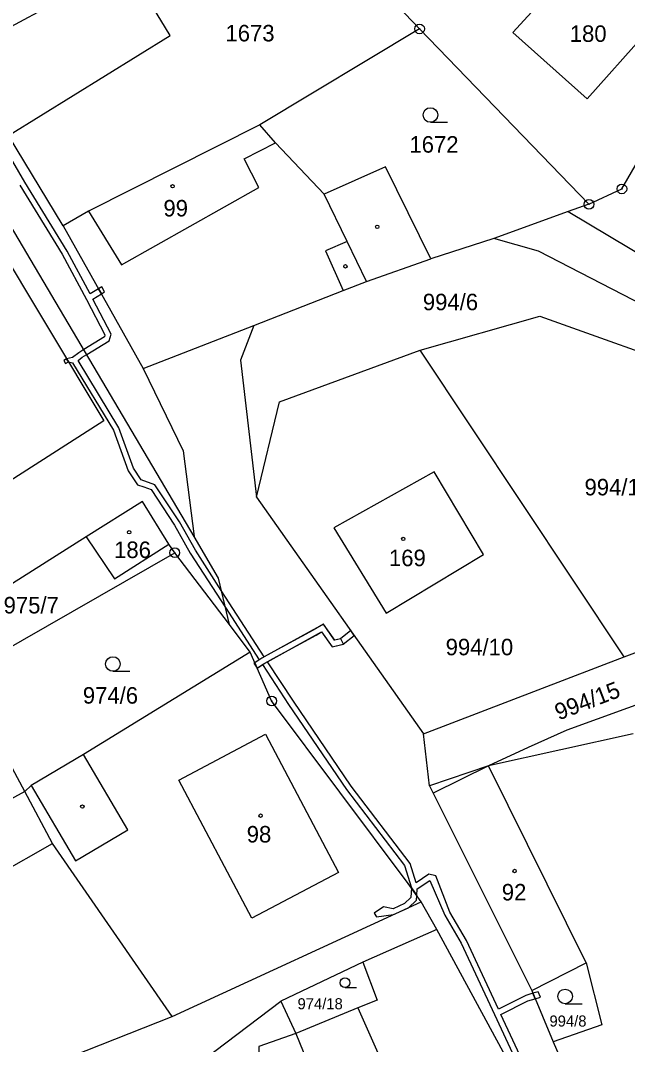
# Model space of a CAD drawing. Extents: x -680203 to -673936, y -1102717 to -1093650.
# Drawn here: x -676663.1 to -676600.6, y -1100837.8 to -1100732.3 of the extents above; entities that cross this region are included whole.
import ezdxf

# ---------------------------------------------------------------- set-up
doc = ezdxf.new("R2010")
doc.units = 0
for name, color, linetype in [('SOxx02xx_Koleje_param další_Popis10', 7, 'Continuous'), ('SOxxxxxx_Koleje_hlavní_body_Popis10', 7, 'Continuous'), ('SOxxxxxx_Koleje_LN_parametry_Popis10', 7, 'Continuous'), ('SOxxxxxx_Koleje_param další_Popis10', 7, 'Continuous'), ('SOxxxxxx_Osa_bod_P', 7, 'Continuous'), ('SOxxxxxx_Staničení_Popis10', 7, 'Continuous'), ('x_prac', 7, 'Continuous')]:
    doc.layers.add(name, color=color, linetype=linetype)

msp = doc.modelspace()

# ---------------------------------------------------------------- linework, layer by layer
at = {"layer": 'SOxx02xx_Koleje_param další_Popis10'}
for centre, radius in [((-676622.04, -1100733.21), 0.5), ((-676622.04, -1100733.21), 0.0303), ((-676601.2, -1100749.69), 0.5), ((-676601.2, -1100749.69), 0.0303), ((-676604.59, -1100751.28), 0.5), ((-676604.59, -1100751.28), 0.0303), ((-676647.25, -1100787.16), 0.5), ((-676647.25, -1100787.16), 0.0303), ((-676637.28, -1100802.43), 0.5), ((-676637.28, -1100802.43), 0.0303)]:
    msp.add_circle(centre, radius, dxfattribs=at)
at = {"layer": 'SOxxxxxx_Koleje_hlavní_body_Popis10'}
for p, q in [((-676620.92, -1100742.83), (-676619.17, -1100742.83)), ((-676653.62, -1100799.38), (-676651.87, -1100799.38)), ((-676629.71, -1100831.95), (-676628.54, -1100831.95)), ((-676607.05, -1100833.62), (-676605.3, -1100833.62))]:
    msp.add_line(p, q, dxfattribs=at)
for centre, radius in [((-676620.92, -1100742.08), 0.75), ((-676653.62, -1100798.63), 0.75), ((-676629.72, -1100831.45), 0.502), ((-676607.05, -1100832.87), 0.75)]:
    msp.add_circle(centre, radius, dxfattribs=at)
at = {"layer": 'SOxxxxxx_Koleje_LN_parametry_Popis10'}
for points in [[(-676610.13, -1100833.1), (-676610.36, -1100832.54), (-676611.11, -1100832.76), (-676613.92, -1100834.19), (-676617.2, -1100827.1), (-676618.93, -1100824.2), (-676620.38, -1100820.46), (-676621.08, -1100820.27), (-676622.4, -1100821.15), (-676623.01, -1100819.19), (-676629.08, -1100811.22), (-676635.03, -1100802.47), (-676637.7, -1100798.39), (-676632.13, -1100795.3), (-676631.04, -1100796.85), (-676629.89, -1100796.57), (-676630.16, -1100796.02), (-676630.78, -1100796.17), (-676631.95, -1100794.52), (-676638.03, -1100797.88), (-676642.46, -1100791.04), (-676645.13, -1100786.9), (-676646.75, -1100783.99), (-676649.29, -1100780.16), (-676650.72, -1100779.67), (-676651.51, -1100778.46), (-676653.01, -1100774.29), (-676657.21, -1100767.37), (-676656.78, -1100767.04), (-676656.32, -1100766.76), (-676654, -1100765.35), (-676653.79, -1100764.65), (-676655.69, -1100761.04), (-676654.81, -1100760.51), (-676655.11, -1100759.99), (-676655.97, -1100760.51), (-676658.34, -1100756.12), (-676662.7, -1100749.01), (-676666.3, -1100742.87)], [(-676663.22, -1100749.32), (-676658.86, -1100756.42), (-676656.35, -1100761.07), (-676654.44, -1100764.71), (-676654.5, -1100764.93), (-676656.63, -1100766.24), (-676657.14, -1100766.56), (-676657.78, -1100767.06), (-676658.39, -1100767.18), (-676658.21, -1100767.49), (-676657.77, -1100767.61), (-676653.55, -1100774.55), (-676652.05, -1100778.72), (-676651.1, -1100780.17), (-676650.44, -1100780.39), (-676649.67, -1100780.66), (-676647.27, -1100784.31), (-676645.65, -1100787.2), (-676642.03, -1100792.8), (-676638.55, -1100798.19), (-676639.01, -1100798.49), (-676638.77, -1100799.04), (-676638.22, -1100798.69), (-676635.53, -1100802.81), (-676629.58, -1100811.56), (-676623.59, -1100819.37), (-676622.88, -1100821.68), (-676622.33, -1100822.46), (-676622.28, -1100821.79), (-676620.98, -1100820.92), (-676619.45, -1100824.5), (-676617.74, -1100827.38), (-676614.33, -1100834.73), (-676610.64, -1100842.63)], [(-676609.97, -1100842.66), (-676613.67, -1100834.74), (-676610.89, -1100833.32), (-676610.13, -1100833.1)]]:
    msp.add_lwpolyline(points, dxfattribs=at)
for points in [[(-676654.77, -1100759.78), (-676655.11, -1100759.99), (-676654.81, -1100760.51), (-676654.48, -1100760.31)], [(-676658.51, -1100767.67), (-676658.21, -1100767.49), (-676658.39, -1100767.18), (-676658.69, -1100767.36)], [(-676638.28, -1100798.02), (-676639.01, -1100798.49), (-676638.77, -1100799.04), (-676637.98, -1100798.54), (-676637.13, -1100798.07), (-676632.7, -1100795.65), (-676632.13, -1100795.31), (-676631.04, -1100796.85), (-676629.92, -1100796.58), (-676628.77, -1100795.68), (-676629.12, -1100795.19), (-676630.18, -1100796.02), (-676630.8, -1100796.17), (-676631.95, -1100794.51), (-676633, -1100795.13), (-676637.41, -1100797.55)], [(-676630.8, -1100796.17), (-676631.95, -1100794.51), (-676633, -1100795.13), (-676637.41, -1100797.55), (-676638.28, -1100798.02), (-676639.01, -1100798.49), (-676638.77, -1100799.04), (-676637.98, -1100798.54), (-676637.13, -1100798.07), (-676632.7, -1100795.65), (-676632.13, -1100795.31), (-676631.04, -1100796.85), (-676629.92, -1100796.58), (-676628.77, -1100795.68), (-676629.12, -1100795.19), (-676630.18, -1100796.02)], [(-676638.77, -1100799.04), (-676639.01, -1100798.49), (-676639.11, -1100798.55)], [(-676622.33, -1100822.46), (-676622.88, -1100821.68), (-676622.94, -1100822.68), (-676623.6, -1100823.3), (-676624.76, -1100823.84), (-676625.74, -1100823.64), (-676626.71, -1100824.28), (-676626.46, -1100824.66), (-676624.72, -1100824.44), (-676623.19, -1100823.74), (-676622.36, -1100822.95)], [(-676609.84, -1100832.38), (-676610.36, -1100832.54), (-676610.13, -1100833.1), (-676609.58, -1100832.93)]]:
    msp.add_lwpolyline(points, close=True, dxfattribs=at)
at = {"layer": 'SOxxxxxx_Koleje_param další_Popis10'}
for centre in [(-676647.48, -1100749.42), (-676626.4, -1100753.6), (-676629.68, -1100757.67), (-676651.95, -1100785.06), (-676623.72, -1100785.74), (-676656.77, -1100813.31), (-676638.41, -1100814.25), (-676612.25, -1100819.95)]:
    msp.add_circle(centre, 0.175, dxfattribs=at)
at = {"layer": 'SOxxxxxx_Staničení_Popis10'}
for p, q in [((-676666.5, -1100734.25), (-676652.22, -1100726.48)), ((-676640.09, -1100746.61), (-676636.87, -1100744.96)), ((-676638.58, -1100749.56), (-676640.09, -1100746.61)), ((-676652.75, -1100757.53), (-676638.58, -1100749.56)), ((-676629.5, -1100755.12), (-676631.88, -1100750.24)), ((-676656.14, -1100751.99), (-676652.75, -1100757.53)), ((-676629.5, -1100755.12), (-676631.72, -1100756.07)), ((-676627.5, -1100759.23), (-676629.5, -1100755.12)), ((-676631.72, -1100756.07), (-676629.9, -1100760.16)), ((-676646.82, -1100810.6), (-676637.89, -1100805.87)), ((-676637.89, -1100805.87), (-676630.39, -1100820.11)), ((-676652.09, -1100815.7), (-676656.66, -1100807.94)), ((-676614.94, -1100809.1), (-676620.63, -1100811.92)), ((-676604.87, -1100829.39), (-676614.94, -1100809.1)), ((-676662.05, -1100811.14), (-676657.49, -1100818.89)), ((-676639.31, -1100824.82), (-676646.82, -1100810.6)), ((-676662.7, -1100811.75), (-676674.85, -1100818.37)), ((-676657.49, -1100818.89), (-676652.09, -1100815.7)), ((-676671.83, -1100823.9), (-676659.84, -1100817.11)), ((-676630.39, -1100820.11), (-676639.31, -1100824.82)), ((-676628.39, -1100834.05), (-676621.17, -1100850.29))]:
    msp.add_line(p, q, dxfattribs=at)
at = {"layer": 'x_prac'}
for p, q in [((-676645.24, -1100785.51), (-676704.94, -1100684.52)), ((-676631.21, -1100723.52), (-676622.04, -1100733.21)), ((-676622.04, -1100733.21), (-676638.5, -1100743.1)), ((-676622.04, -1100733.21), (-676604.59, -1100751.28)), ((-676658.76, -1100753.5), (-676664.39, -1100744.2)), ((-676606.72, -1100752.03), (-676614.4, -1100754.81)), ((-676604.59, -1100751.28), (-676606.72, -1100752.03)), ((-676606.72, -1100752.03), (-676594.79, -1100759.18)), ((-676658.76, -1100753.5), (-676650.49, -1100768.18)), ((-676614.4, -1100754.81), (-676620.89, -1100756.89)), ((-676650.49, -1100768.18), (-676639.11, -1100763.75)), ((-676600.96, -1100797.88), (-676621.98, -1100766.29)), ((-676638.82, -1100781.44), (-676621.62, -1100805.81)), ((-676647.25, -1100787.16), (-676647.87, -1100786.27)), ((-676669.64, -1100800), (-676647.25, -1100787.16)), ((-676641.61, -1100794.55), (-676647.25, -1100787.16)), ((-676600.96, -1100797.88), (-676590.47, -1100793.9)), ((-676639.49, -1100797.4), (-676641.61, -1100794.55)), ((-676621.62, -1100805.81), (-676600.96, -1100797.88)), ((-676662.7, -1100811.75), (-676667.93, -1100802.08)), ((-676621.03, -1100811.18), (-676621.62, -1100805.81)), ((-676600.04, -1100805.82), (-676614.94, -1100809.1)), ((-676610.84, -1100807.23), (-676614.94, -1100809.1)), ((-676614.94, -1100809.1), (-676621.03, -1100811.18)), ((-676659.84, -1100817.11), (-676662.7, -1100811.75)), ((-676647.52, -1100834.92), (-676659.84, -1100817.11)), ((-676647.52, -1100834.92), (-676621.86, -1100823.13)), ((-676620.26, -1100825.98), (-676621.86, -1100823.13)), ((-676620.26, -1100825.98), (-676627.89, -1100829.35)), ((-676609.75, -1100845.32), (-676620.26, -1100825.98)), ((-676627.89, -1100829.35), (-676636.32, -1100833.37)), ((-676610.48, -1100832.25), (-676608.29, -1100837.53)), ((-676651.73, -1100844.99), (-676636.32, -1100833.37)), ((-676636.32, -1100833.37), (-676634.79, -1100836.7)), ((-676634.79, -1100836.7), (-676627.86, -1100853.29)), ((-676608.29, -1100837.53), (-676604.4, -1100846.36))]:
    msp.add_line(p, q, dxfattribs=at)
for points in [[(-676664.39, -1100744.2), (-676647.73, -1100733.89), (-676652.22, -1100726.48), (-676655.94, -1100720.27)], [(-676612.44, -1100733.57), (-676604.79, -1100740.41), (-676598.82, -1100733.77), (-676599.68, -1100732.94), (-676598.07, -1100731.04), (-676604.72, -1100725.14), (-676612.44, -1100733.57)], [(-676604.59, -1100751.28), (-676601.2, -1100749.69), (-676591.14, -1100732.33)], [(-676638.5, -1100743.1), (-676656.14, -1100751.99), (-676658.76, -1100753.5)], [(-676620.89, -1100756.89), (-676625.53, -1100747.43), (-676631.88, -1100750.24), (-676636.87, -1100744.96), (-676638.5, -1100743.1)], [(-676665.98, -1100754.56), (-676654.55, -1100773.58), (-676677.03, -1100787.96), (-676689.32, -1100767.17)], [(-676581.63, -1100770.64), (-676609.8, -1100756.11), (-676614.4, -1100754.81)], [(-676639.11, -1100763.75), (-676629.9, -1100760.16), (-676627.5, -1100759.23), (-676620.89, -1100756.89)], [(-676639.11, -1100763.75), (-676640.48, -1100767.34), (-676638.82, -1100781.44)], [(-676621.98, -1100766.29), (-676609.66, -1100762.79), (-676592.74, -1100768.85)], [(-676638.82, -1100781.44), (-676636.46, -1100771.62), (-676621.98, -1100766.29)], [(-676650.49, -1100768.18), (-676646.38, -1100776.66), (-676645.24, -1100785.51)], [(-676620.53, -1100778.85), (-676630.88, -1100784.6), (-676625.47, -1100793.39), (-676615.44, -1100787.35), (-676620.53, -1100778.85)], [(-676647.87, -1100786.27), (-676650.58, -1100781.9), (-676656.37, -1100785.52)], [(-676656.37, -1100785.52), (-676672.63, -1100795.8), (-676669.64, -1100800)], [(-676656.37, -1100785.52), (-676653.46, -1100789.86), (-676647.87, -1100786.27)], [(-676641.61, -1100794.55), (-676642.76, -1100789.77), (-676645.24, -1100785.51)], [(-676580.24, -1100796.33), (-676591.24, -1100799.79), (-676606.88, -1100805.43), (-676610.84, -1100807.23)], [(-676639.49, -1100797.4), (-676656.66, -1100807.94), (-676662.05, -1100811.14), (-676662.7, -1100811.75)], [(-676621.86, -1100823.13), (-676623.2, -1100821.22), (-676637.28, -1100802.43), (-676639.49, -1100797.4)], [(-676621.03, -1100811.18), (-676620.63, -1100811.92), (-676610.48, -1100832.25)], [(-676627.89, -1100829.35), (-676626.4, -1100833.25), (-676628.39, -1100834.05), (-676634.79, -1100836.7)], [(-676610.48, -1100832.25), (-676604.87, -1100829.39), (-676603.26, -1100835.79), (-676608.29, -1100837.53)], [(-676671.54, -1100844.46), (-676665.22, -1100841.95), (-676647.52, -1100834.92)], [(-676634.79, -1100836.7), (-676638.58, -1100838.02), (-676638.47, -1100854.76), (-676648.51, -1100858.05)]]:
    msp.add_lwpolyline(points, dxfattribs=at)

# ---------------------------------------------------------------- texts
at = {"layer": 'SOxxxxxx_Osa_bod_P'}
for s, height, p in [('1673', 1.7, (-676642.03, -1100734.5)), ('180', 1.7, (-676606.57, -1100734.55)), ('1672', 1.7, (-676623.08, -1100745.96)), ('99', 1.7, (-676648.42, -1100752.53)), ('994/6', 1.7, (-676621.7, -1100762.19)), ('994/11', 1.7, (-676605.05, -1100781.26)), ('186', 1.7, (-676653.5, -1100787.71)), ('169', 1.7, (-676625.19, -1100788.55)), ('975/7', 1.7, (-676664.88, -1100793.42)), ('994/10', 1.7, (-676619.35, -1100797.73)), ('974/6', 1.7, (-676656.72, -1100802.71)), ('98', 1.7, (-676639.84, -1100817.01)), ('92', 1.7, (-676613.57, -1100822.98)), ('974/18', 1.14, (-676634.61, -1100834.19)), ('994/8', 1.14, (-676608.66, -1100835.97))]:
    msp.add_text(s, height=height, dxfattribs=at).set_placement(p)
msp.add_text('994/15', height=1.7, rotation=21, dxfattribs=at).set_placement((-676607.71, -1100804.45))

doc.saveas('drawing.dxf')
